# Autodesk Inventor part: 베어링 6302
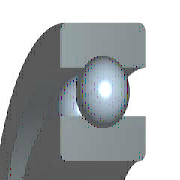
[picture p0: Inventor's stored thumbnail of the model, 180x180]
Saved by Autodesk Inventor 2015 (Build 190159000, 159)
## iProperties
IsCustomPart: 1
Created: 2012-02
Part Number: 베어링 6302
Material: 강철, 연강
Document SubType Name: Modeling
Standard: JIS B 1521
Designer: mdu-01
Standards Organization: JIS
Language: ko-KR
Size Designation: 6302 15x42x13
Categories: <MemberInstance><Categories><Category DisplayName="샤프트 부품" InternalName="7f7aeb1f-a693-4053-b835-cee3144e0d98" Mnemonic="SHFT"><Category DisplayName="베어링" Inter
Density: 1 g/cm^3
Appearance: 노란색
Author: mdu-01
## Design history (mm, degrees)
sketch "스케치" dims "d0" = 7.02 (= -0.26 x WD + 0.26 x BD)
  geometry: L1 (2.99, 14.25)-(10.01, 14.25); L2 (6.5, 14.25)-(6.5, 10.74); L3 (6.5, 14.25)-(6.5, 17.76); L4 (3.892, 11.901)-(0, 11.901); L5 (0, 7.5)-(13, 7.5); L6 (3.892, 16.599)-(0, 16.599); L7 (0, 21)-(13, 21); L8 (13, 7.5)-(13, 11.901); L9 (9.108, 11.901)-(13, 11.901); L10 (9.108, 16.599)-(13, 16.599); L11 (13, 21)-(13, 16.599); L12 (-1.4, 0)-(8.4, 0) reference; L13 (0, -0.3)-(0, 5.3) reference
  constraints: 22 end point, 4 point on line, 2 collinear, 2 perpendicular, 2 symmetric about line, 1 midpoint, 1 parallel, 14 other
  dimensions: "d9" = 15 diameter of L5 L12 (= WD); "d11" = 42 diameter of L7 L12 (= BD); "d12" = 13 distance between parallel lines of L8 L13 (= KB); "d13" = 23.802 diameter of L9 L12 (= 0.326 x BD + 0.674 x WD)
revolve "본체" stored, may be unused: angle "d6" = 90 deg
revolve "볼" stored, may be unused: angle "d7" = 90 deg
pattern_circular "IDS_ARRAYBALL[SIMPL:T]" dims angle "d3" = 360 deg
body "Solid1"
fillet "모깎기1" dims "d1" = 1 (= KRS)
other parameters: "WD" = 15 [user parameter; used in 5 equation terms], "BD" = 42 [user parameter; used in 5 equation terms], "KB" = 13 [user parameter; used in 1 equation term], "KRS" = 1 [user parameter; used in 1 equation term], "d4" = 0, "d5" = 0, "d8" = 0, "d14" = 0, "d15" = 0, "BBA" = 0 [user parameter], "BC0" = 5400000 [user parameter], "BC" = 1.14e+07 [user parameter], "BR" = 21 (= 0.5 x BD) [user parameter], "WR" = 7.5 (= 0.5 x WD) [user parameter]
